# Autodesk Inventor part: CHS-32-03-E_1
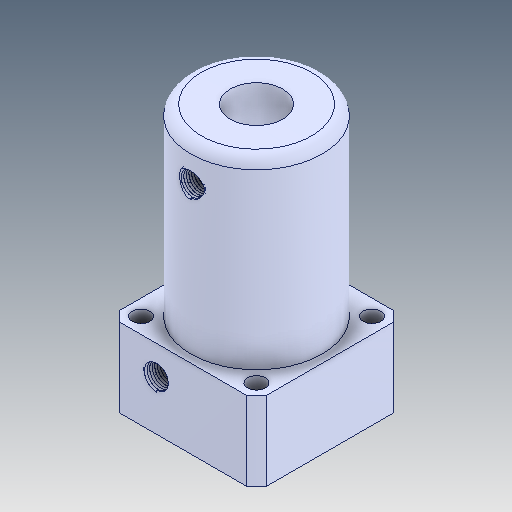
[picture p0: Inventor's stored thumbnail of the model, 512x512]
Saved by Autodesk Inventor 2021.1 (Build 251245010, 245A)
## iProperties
Created: 2021-05
Part Number: CHS-32-03-E_1
Material: Ogólny
Document SubType Name: Modeling
Designer: user
Density: 1 g/cm^3
Appearance: Domyślna
Author: user
Revision Number: ÈÎºÎ
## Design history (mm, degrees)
feature "NONE"
node "Bryła1"
